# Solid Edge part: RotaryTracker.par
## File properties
Author: wojci
Template: ISO Metric Part.par
Last saved by: wojci
Revision: 42
Application: Solid Edge
Username: wojci
Accuracy: 0.990
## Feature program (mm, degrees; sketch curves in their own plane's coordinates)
sketch for "BaseBody" plane through (0, 0, 0) normal (0, 0, 1) x-axis (1, 0, 0)
  bspline degree 3 poles (1.5379, -11.7359) (-1.4721, -13.7318) (-9.1676, -14.1888) (-15.7878, -10.1835) (-18.4729, -7.1989) (-21.9311, -1.3839) (-22.9867, 6.2391) (-21.8018, 12.5091) (-19.0542, 18.723) (-14.7728, 23.9676) (-8.8713, 28.2153) (-3.826, 30.2201) (0.5696, 31.2322) (3.7846, 31.6196) (6.4482, 31.6319) (7.8721, 31.5463) (8.3169, 31.5201) (8.5, 31.5) knots 0 0.0234 0.0806 0.1504 0.2402 0.3357 0.437 0.5006 0.6217 0.7176 0.8332 0.8617 0.934 0.9776 0.9919 1 multiplicities 4 1 1 1 1 1 1 1 1 1 1 1 1 1 1 4
  line (8.5, 0) -> (8.5, 31.5)
  bspline degree 3 poles (1.5379, -11.7359) (3.3667, -10.5232) (4.4898, -9.0766) (7.0488, -4.7502) knots 0 1 multiplicities 4 4
extrude "BaseBody" add finite 12 along +normal
sketch for "unnamed Cutout 1" plane through (0, 0, 0) normal (0, 0, 1) x-axis (1, 0, 0)
  line (-6.25, 20) -> (-6.25, 0)
  line (6.25, 0) -> (6.25, 20)
extrude "unnamed Cutout 1" cut finite 4.5 along +normal
sketch for "unnamed Hole 1" plane through (0, 0, 12) normal (0, 0, 1) x-axis (0, 1, 0)
  hole centre (21, 0) bore radius 1.35
  dimension (linear) = 21
hole "unnamed Hole 1" through
sketch for "unnamed Hole 2" plane through (0, 0, 12) normal (0, 0, 1) x-axis (0, 1, 0)
  hole centre (16, 0) bore radius 1.35
hole "unnamed Hole 2" through
holes "Holes" diameter 2.7: "unnamed Hole 1", "unnamed Hole 2"  CounterBoreDepth = 3.7 mm
sketch used by "unnamed Cutout 2" plane through (-7.1473, 15, 12) normal (0, 0, 1) x-axis (0, -1, 0)
extrude "unnamed Cutout 2" cut finite 5 along -normal
sketch for "unnamed Hole 3" plane through (-5.7387, 11.5148, 12) normal (0, 0, 1) x-axis (0, -1, 0)
  hole centre (11.5148, 5.7387) bore radius 1.8
hole "unnamed Hole 3" through
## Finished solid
Body 1: solid body, 19 faces, 42 edges, 24 vertices.
  Faces by surface: plane 9, cylinder 8, swept 2
  Edges by curve: line 22, circle 16, spline 4
Bounding box of the edges (mm; curved faces can reach further): 31.084 x 45.394 x 12.000, from (-22.5835, -13.7771, 0) to (8.5, 31.6168, 12).
Cylindrical faces by radius (mm): R1.35 x2, R1.8 x1, R2.75 x2, R6.25 x2, R8.5 x1
Planar faces by outward normal: +x 3, +z 2, -x 2, -z 2
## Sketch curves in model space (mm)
line (-22.5854, 31.5, 12) -> (8.5, 31.5, 12)
line (8.5, 31.5, 12) -> (8.5, -8.5, 12)
line (8.5, -8.5, 12) -> (-22.5854, -8.5, 12)
line (-22.5854, -8.5, 12) -> (-22.5854, 31.5, 12)
arc centre (0, 0, 0) radius 6.25 from (6.25, 0, 0) through (-0.1852, -6.2473, 0) to (-6.25, 0, 0)
line (6.25, 0, 0) -> (6.25, 20, 0)
arc centre (0, 20, 0) radius 6.25 from (-6.25, 20, 0) through (0.1852, 26.2473, 0) to (6.25, 20, 0)
line (-6.25, 20, 0) -> (-6.25, 0, 0)
arc centre (0, 16, 12) radius 2.75 from (2.75, 16, 12) through (-0.0815, 13.2512, 12) to (-2.75, 16, 12)
line (-2.75, 16, 12) -> (-2.75, 21, 12)
arc centre (0, 21, 12) radius 2.75 from (-2.75, 21, 12) through (0.0815, 23.7488, 12) to (2.75, 21, 12)
line (2.75, 21, 12) -> (2.75, 16, 12)
spline (1.5379, -11.7359, 0) -> (-19.504, 17.3694, 0) -> (8.5, 31.5, 0)
spline (1.5379, -11.7359, 0) -> (4.0195, -9.4107, 0) -> (7.0488, -4.7502, 0)
arc centre (0, 0, 0) radius 8.5 from (8.5, 0, 0) through (8.1291, -2.4834, 0) to (7.0488, -4.7502, 0)
line (8.5, 0, 0) -> (8.5, 31.5, 0)
line (0, 0, 0) -> (0, 0, 8)
line (0, 0, 0) -> (5.4637, -6.5114, 0)
line (0, 0, 0) -> (8.5, -8.5, 0)
line (0, 0, 0) -> (-8.5, -8.5, 0)
line (8.5, -8.5, 0) -> (-8.5, -8.5, 0)
line (0, -8.5, 0) -> (0, 28.5, 0)
circle centre (0, 20, 0) radius 8.5
circle centre (0, 0, 0) radius 8.5
line (0, 0, 0) -> (0, -8.5, 0)
line (0, 0, 0) -> (8.5, 31.5, 0)
line (8.5, -8.5, 0) -> (8.5, 31.5, 0)
line (8.5, 28.5, 0) -> (8.5, -8.5, 0)
line (-8.5, -8.5, 0) -> (-8.5, 28.5, 0)
line (-8.5, 28.5, 0) -> (8.5, 28.5, 0)
line (8.5, 20, 0) -> (8.5, 0, 0)
line (8.5, 0, 0) -> (-8.5, 0, 0)
line (-8.5, 0, 0) -> (-8.5, 20, 0)
line (-8.5, 20, 0) -> (8.5, 20, 0)
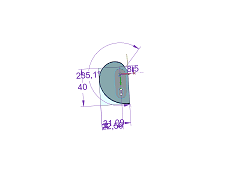
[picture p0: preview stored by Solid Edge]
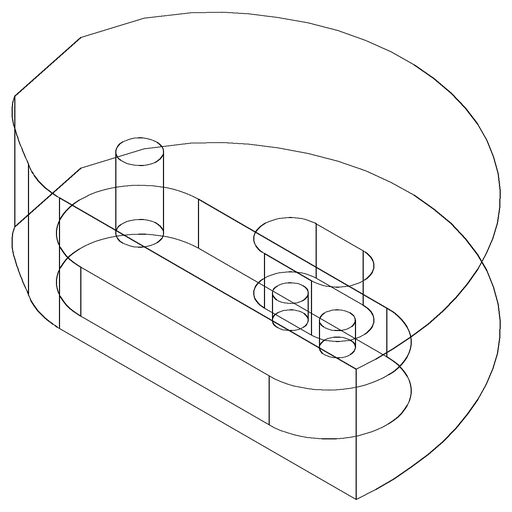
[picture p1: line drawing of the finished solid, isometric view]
